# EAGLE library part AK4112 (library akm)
Digital Audio Receiver (DIR) High Feature, 24-Bit, 96 kHz
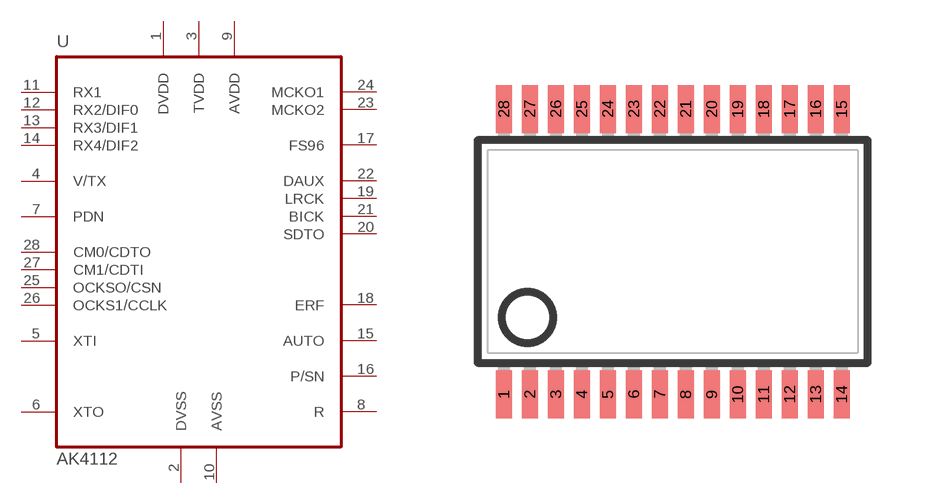
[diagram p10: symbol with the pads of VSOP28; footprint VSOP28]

Designator prefix U

## AK4112  [VSOP28]
1  DVDD  pwr
2  DVSS  pwr
3  TVDD  pwr
4  V/TX  out
5  XTI  in
6  XTO  out
7  PDN  in
8  R  pas
9  AVDD  pwr
10  AVSS  pwr
11  RX1  in
12  RX2/DIF0  in
13  RX3/DIF1  in
14  RX4/DIF2  in
15  AUTO
16  P/SN  in
17  FS96
18  ERF
19  LRCK
20  SDTO  out
21  BICK
22  DAUX
23  MCKO2  out
24  MCKO1  out
25  OCKSO/CSN
26  OCKS1/CCLK
27  CM1/CDTI
28  CM0/CDTO

## Footprint VSOP28 (pad centres in mm)
VSOP28 9.8 x 5.6 mm, pitch .65 mm
smd 0.4 x 1.2: 1 -4.225,-3.57; 2 -3.575,-3.57; 3 -2.925,-3.57; 4 -2.275,-3.57; 5 -1.625,-3.57; 6 -0.975,-3.57; 7 -0.325,-3.57; 8 0.325,-3.57; 9 0.975,-3.57; 10 1.625,-3.57; 11 2.275,-3.57; 12 2.925,-3.57; 13 3.575,-3.57; 14 4.225,-3.57; 15 4.225,3.57; 16 3.575,3.57; 17 2.925,3.57; 18 2.275,3.57; 19 1.625,3.57; 20 0.975,3.57; 21 0.325,3.57; 22 -0.325,3.57; 23 -0.975,3.57; 24 -1.625,3.57; 25 -2.275,3.57; 26 -2.925,3.57; 27 -3.575,3.57; 28 -4.225,3.57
